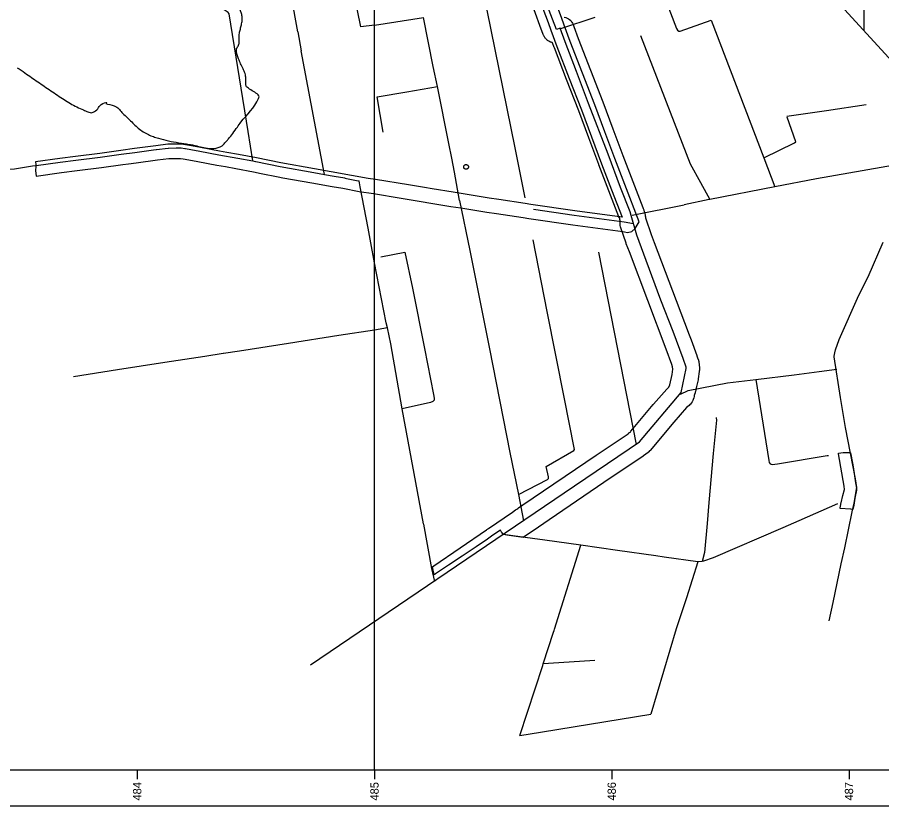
# Model space of a CAD drawing. Extents: x 468834 to 503362, y 294936 to 320859.
# Drawn here: x 483494 to 487137, y 294936 to 298258 of the extents above; entities that cross this region are included whole.
import ezdxf

# ---------------------------------------------------------------- set-up
doc = ezdxf.new("R2010")
doc.units = 0
for name, color, linetype in [('7311020103_no 10 līdz 25 kilometriem garas dabiskas ūdensteces vides un dabas resursu aizsardzības aizsargjoslas teritorija lauku apvidos', 7, 'Continuous'), ('7311080102_vides un dabas resursu aizsardzības aizsargjoslas teritorija ap purvu ar platību lielāku par 100 hektāriem', 7, 'Continuous'), ('7311090700_stingra režīma vides un dabas resursu aizsardzības aizsargjoslas teritorija ap pazemes ūdens ņemšanas vietu', 7, 'Continuous'), ('7312030303_ekspluatācijas aizsargjoslas teritorija gar valsts vietējiem un pašvaldību autoceļiem lauku apvidos', 7, 'Continuous'), ('7312070202_navigācijas tehniskā līdzekļa aviācijas gaisa kuģu lidojumu drošības nodrošināšanai tālās ietekmes zona', 7, 'Continuous'), ('aizkrāsojums-lidlauka tālās ietekmes zona', 7, 'Continuous'), ('Koplietošanas novadgrāvis', 7, 'Continuous'), ('ramis', 7, 'Continuous'), ('Valsts nozīmes udensnotekas', 7, 'Continuous')]:
    doc.layers.add(name, color=color, linetype=linetype)

msp = doc.modelspace()

# ---------------------------------------------------------------- linework, layer by layer
at = {"layer": '7311020103_no 10 līdz 25 kilometriem garas dabiskas ūdensteces vides un dabas resursu aizsardzības aizsargjoslas teritorija lauku apvidos'}
msp.add_lwpolyline([(485799.4, 298258.6), (485805.5, 298257), (485811.4, 298254.7), (485816.9, 298251.7), (485821.9, 298248), (485826.5, 298243.7), (485830.5, 298238.9), (485831.8, 298236.8), (485833.9, 298233.6), (485836.6, 298227.9), (485837, 298226.8), (485840, 298218.5), (485858.7, 298168.1), (485910, 298035.3), (485961.4, 297902.3), (485961.6, 297901.7), (486004.1, 297788.2), (486046.6, 297675.3), (486088.6, 297565.9), (486130.8, 297456.4), (486132.4, 297452.3), (486132.6, 297451.7), (486134.6, 297446.6), (486135.4, 297444.2), (486136.3, 297441.1), (486136.9, 297438.3), (486137.4, 297437), (486138.3, 297433.8), (486139.1, 297430.6), (486139.1, 297430.5), (486139.9, 297426.6), (486140, 297426), (486140.2, 297424.7), (486140.9, 297420.8), (486141, 297420.5), (486141, 297420.3), (486141.1, 297419.7), (486141.1, 297419.5), (486141.2, 297419.2), (486142, 297414.1), (486142.1, 297413.3), (486142.2, 297412.8), (486142.2, 297412.4), (486165.6, 297343), (486178.6, 297309), (486178.6, 297308.9), (486240.3, 297146.1), (486321.4, 296931.7), (486322, 296929.6), (486322.7, 296928.3), (486323.2, 296926.8), (486333.7, 296899.2), (486333.8, 296899), (486358.2, 296833.4), (486358.3, 296833), (486358.4, 296832.9), (486358.6, 296832.1), (486358.7, 296832), (486358.7, 296831.9), (486358.8, 296831.6), (486361.5, 296823.6), (486361.6, 296823.3), (486364.8, 296813.5), (486365.7, 296810.7), (486365.8, 296810.3), (486366, 296809.6), (486366.6, 296806.7), (486367.2, 296803.5), (486367.2, 296803), (486367.3, 296802.2), (486367.6, 296799.4), (486367.6, 296798.8), (486368.9, 296775.7), (486368.9, 296773.3), (486368.9, 296772.7), (486368.8, 296769.2), (486368.7, 296767.9), (486368.7, 296767.3), (486368.5, 296765.4), (486368.4, 296764.9), (486364.2, 296735), (486364, 296734), (486364, 296733.8), (486363.7, 296732), (486363.6, 296731.8), (486363.6, 296731.6), (486363.4, 296730.6), (486357, 296702.2), (486352.2, 296680.9), (486352.2, 296680.7), (486351.8, 296679), (486351.7, 296678.6), (486351.6, 296678.3), (486350.7, 296675.3), (486350.6, 296674.9), (486350.5, 296674.8), (486350, 296673.3), (486346.6, 296664.1), (486346.3, 296660.4), (486345.1, 296654.2), (486343.2, 296648.2), (486341.2, 296643.9), (486339.3, 296640.1), (486338.4, 296638.4), (486337.9, 296637.5), (486334.6, 296632.2), (486331.4, 296628.3), (486330.3, 296627), (486329.4, 296626), (486325.8, 296622.5), (486315.1, 296613.2), (486261.4, 296552.7), (486161.4, 296433.4), (486159.7, 296431.5), (486159.1, 296430.9), (486155.3, 296427.2), (486154.7, 296426.7), (486153.9, 296426), (486152.7, 296425), (486133.4, 296410.1), (486132.6, 296409.5), (486131, 296408.3), (486130.2, 296407.8), (485997.7, 296319.2), (485735.3, 296140.4), (485667.9, 296094.5), (485640.1, 296075.5), (485626.8, 296066.5), (485558, 296076.4), (485541.3, 296078.8), (485537.1, 296086.2), (485537, 296086.3), (485530.6, 296097.6), (485498.7, 296075.6), (485475.8, 296059.8), (485427.9, 296027), (485369.8, 295987.7), (485312.2, 295949.2), (485256.7, 295913.1), (485250.5, 295909), (485244, 295943.3), (485249.7, 295947.2), (485471.3, 296098.4), (485472.7, 296099.3), (485475.6, 296100.9), (485478, 296102.9), (485480.3, 296104.5), (485580.7, 296173), (485594.1, 296182.2), (485594.5, 296182.5), (485597.3, 296184.2), (485598.9, 296185), (485599.4, 296185.5), (485603.1, 296188.3), (485607.1, 296191), (485625, 296203.2), (485933.9, 296413.7), (486068.2, 296503.5), (486069.2, 296504.1), (486069.5, 296504.3), (486069.5, 296504.3), (486071.9, 296506.5), (486074.2, 296508.4), (486078, 296511.4), (486080.7, 296514.6), (486097.2, 296534.3), (486174.6, 296626.6), (486174.8, 296626.8), (486174.9, 296626.9), (486175.3, 296627.5), (486175.4, 296627.5), (486175.4, 296627.6), (486175.6, 296627.8), (486232.3, 296691.6), (486233.3, 296692.8), (486233.6, 296693.1), (486234.6, 296694.1), (486235.9, 296695.3), (486236.2, 296695.6), (486237.3, 296696.6), (486237.4, 296696.7), (486240, 296699), (486243.8, 296709), (486253.6, 296752.9), (486256.7, 296775.2), (486256.2, 296785.3), (486252.9, 296795.3), (486228.9, 296859.7), (486073.9, 297269.2), (486060.6, 297304.1), (486060.4, 297304.6), (486060, 297305.7), (486059.8, 297306.2), (486038, 297371.1), (486036.9, 297374.7), (486035.7, 297380.8), (486035.3, 297387.1), (486035.4, 297387.7), (486035.5, 297388.7), (486035.3, 297389.9), (486035.2, 297393.2), (486035.2, 297393.4), (486035.2, 297396.9), (486035.1, 297398.8), (486034.6, 297401.9), (486033.8, 297406.2), (486033.4, 297408.2), (486033.3, 297408.9), (486033, 297409.8), (486031.9, 297412.7), (486030.1, 297417.5), (486030, 297417.5), (485987.8, 297527.1), (485987.8, 297527.1), (485945.7, 297636.7), (485945.6, 297637), (485903, 297750.2), (485902.9, 297750.3), (485860.6, 297863.4), (485809.2, 297996.4), (485809.2, 297996.4), (485757.8, 298129.6), (485757.6, 298130.2), (485749.9, 298150.8), (485748.7, 298151.1), (485748.1, 298151.3), (485746.6, 298151.7), (485744, 298152.5), (485741, 298153.7), (485738, 298155), (485735.1, 298156.6), (485732.3, 298158.3), (485729.7, 298160.2), (485729.2, 298160.5), (485728, 298161.5), (485725.9, 298163.2), (485723.5, 298165.5), (485721.3, 298167.9), (485719.2, 298170.4), (485717.3, 298173), (485715.6, 298175.8), (485715.3, 298176.3), (485714.5, 298177.7), (485713.3, 298180.1), (485711.9, 298183.1), (485711.2, 298184.8), (485697.1, 298222.9), (485659.6, 298323.9)], dxfattribs=at)
msp.add_lwpolyline([(487019.4, 296202.7), (487015.1, 296183.8), (487007.6, 296185.5), (487006.3, 296185.6), (486962.3, 296189), (486964, 296200.5), (486964.6, 296203.6), (486964.9, 296206.4), (486965.4, 296209.7), (486966.1, 296212.6), (486974.2, 296243.5), (486980.1, 296268.4), (486979.5, 296281.8), (486955.7, 296418.7), (486955.2, 296421.4), (486964.7, 296423), (486974.6, 296423.9), (486987.2, 296424.2), (486999.4, 296423.9), (487001.5, 296423.8), (487005.7, 296423.1), (487015.4, 296371.7), (487022, 296336.3), (487027.3, 296296.4), (487030.8, 296274.7), (487031.3, 296265.3), (487024.4, 296231.6)], close=True, dxfattribs=at)
at = {"layer": '7311080102_vides un dabas resursu aizsardzības aizsargjoslas teritorija ap purvu ar platību lielāku par 100 hektāriem'}
for points in [[(484457.5, 297971.9), (484457.5, 298000), (484454, 298020.7), (484445.6, 298041.3), (484435.5, 298062.1), (484426.8, 298083.1), (484417.6, 298118.3), (484418.7, 298125.8), (484422.5, 298133.1), (484426.7, 298140.5), (484429.1, 298148.1), (484429.4, 298156.4), (484429.1, 298164.8), (484428.8, 298173.2), (484429.1, 298181.5), (484432, 298199.5), (484436.5, 298217.4), (484440.6, 298235.3), (484442.3, 298253.1), (484440.1, 298269.4), (484435, 298285.5), (484429.4, 298301.7), (484425.8, 298317.9), (484425.8, 298338), (484433, 298359.2), (484439.6, 298368), (484446.8, 298376.1), (484454, 298383.9), (484460.8, 298392.2), (484487.2, 298427.1)], [(483494.1, 298045.6), (483526.3, 298023.6), (483580.6, 297986), (483635.2, 297948.4), (483691.1, 297911), (483717.8, 297894.8), (483745.3, 297880.3), (483773, 297867.4), (483791.5, 297859.6)], [(484421.6, 297795.3), (484436.9, 297816.5), (484511.2, 297915.6), (484513.1, 297923.3), (484509.1, 297930.7), (484489.9, 297945.1), (484468, 297958.8), (484460.4, 297965.4), (484457.5, 297971.9)], [(483791.5, 297859.6), (483800.6, 297856.2), (483818.9, 297860.3), (483836.9, 297877.5), (483854.6, 297894.8), (483871.9, 297898.6), (483868.7, 297897.1), (483894.6, 297887.5), (483931.5, 297861.3), (483966.9, 297826.2), (484004.2, 297790.7), (484046.8, 297763.4), (484067.7, 297755.1), (484088.8, 297748.2), (484131.6, 297737.4), (484174.8, 297729.4), (484218, 297722.6), (484236.5, 297719), (484295.1, 297706.2), (484332.3, 297706.2), (484363.8, 297722.6), (484369.2, 297728.3), (484374.5, 297733.9), (484384.4, 297745.4), (484402.4, 297768.9), (484421.6, 297795.3)]]:
    msp.add_spline(points, degree=3, dxfattribs=at)
at = {"layer": '7311090700_stingra režīma vides un dabas resursu aizsardzības aizsargjoslas teritorija ap pazemes ūdens ņemšanas vietu'}
msp.add_lwpolyline([(485395.5, 297627.5), (485395.5, 297626.6), (485395.4, 297625.8), (485395.2, 297624.9), (485394.9, 297624.1), (485394.6, 297623.3), (485394.2, 297622.5), (485393.7, 297621.8), (485393.2, 297621.1), (485392.6, 297620.4), (485391.9, 297619.8), (485391.2, 297619.3), (485390.5, 297618.8), (485389.7, 297618.4), (485388.9, 297618.1), (485388.1, 297617.9), (485387.2, 297617.7), (485386.4, 297617.5), (485385.5, 297617.5), (485384.6, 297617.5), (485383.8, 297617.7), (485382.9, 297617.9), (485382.1, 297618.1), (485381.3, 297618.4), (485380.5, 297618.8), (485379.8, 297619.3), (485379.1, 297619.8), (485378.4, 297620.4), (485377.8, 297621.1), (485377.3, 297621.8), (485376.8, 297622.5), (485376.4, 297623.3), (485376.1, 297624.1), (485375.9, 297624.9), (485375.7, 297625.8), (485375.5, 297626.6), (485375.5, 297627.5), (485375.5, 297628.4), (485375.7, 297629.2), (485375.9, 297630.1), (485376.1, 297630.9), (485376.4, 297631.7), (485376.8, 297632.5), (485377.3, 297633.2), (485377.8, 297633.9), (485378.4, 297634.6), (485379.1, 297635.2), (485379.8, 297635.7), (485380.5, 297636.2), (485381.3, 297636.6), (485382.1, 297636.9), (485382.9, 297637.2), (485383.8, 297637.4), (485384.6, 297637.5), (485385.5, 297637.5), (485386.4, 297637.5), (485387.2, 297637.4), (485388.1, 297637.2), (485388.9, 297636.9), (485389.7, 297636.6), (485390.5, 297636.2), (485391.2, 297635.7), (485391.9, 297635.2), (485392.6, 297634.6), (485393.2, 297633.9), (485393.7, 297633.2), (485394.2, 297632.5), (485394.6, 297631.7), (485394.9, 297630.9), (485395.2, 297630.1), (485395.4, 297629.2), (485395.5, 297628.4)], close=True, dxfattribs=at)
at = {"layer": '7312030303_ekspluatācijas aizsargjoslas teritorija gar valsts vietējiem un pašvaldību autoceļiem lauku apvidos'}
for p, q in [((485742.7, 298204.1), (485768.7, 298134.1)), ((485927.7, 297888.9), (485876.1, 298022.2)), ((485970.1, 297775.5), (485927.7, 297888.9)), ((485913.9, 297754.4), (485956.6, 297641)), ((483987.6, 297704.5), (483930.4, 297696.5)), ((484203.2, 297721), (484185.6, 297723.4)), ((484604.4, 297644.1), (484501.9, 297665.8)), ((483570.2, 297648.9), (483572.3, 297637.6)), ((483571.7, 297629.2), (483570.3, 297612.7)), ((483572.3, 297637.6), (483571.7, 297629.2)), ((484254.8, 297650.4), (484335.4, 297635.3)), ((484335.4, 297635.3), (484372.1, 297628.6)), ((484372.1, 297628.6), (484415.5, 297620.6)), ((483570.3, 297612.7), (483574.3, 297588.9)), ((484415.5, 297620.6), (484490.3, 297607)), ((484490.3, 297607), (484522.5, 297600.1)), ((484522.5, 297600.1), (484593.1, 297585.2)), ((484593.1, 297585.2), (484613.2, 297581.8)), ((485004.5, 297574.5), (484973.3, 297578.7)), ((485143.3, 297551.5), (485004.5, 297574.5)), ((485211, 297540.3), (485143.3, 297551.5)), ((486114.9, 297396.7), (486054.8, 297552.9)), ((484935.1, 297523.4), (484995.5, 297515.1)), ((484995.5, 297515.1), (485112.1, 297495.9)), ((485243.3, 297535), (485211, 297540.3)), ((485331.5, 297520.4), (485243.3, 297535)), ((485373.7, 297513.7), (485331.5, 297520.4)), ((485482.9, 297496.2), (485373.7, 297513.7)), ((485523, 297490.1), (485482.9, 297496.2)), ((485634.5, 297473.1), (485523, 297490.1)), ((485659.1, 297469.5), (485634.5, 297473.1)), ((485844.3, 297443), (485659.1, 297469.5)), ((486043.4, 297415.6), (485844.3, 297443)), ((485650.6, 297410.1), (485836, 297383.6)), ((485836, 297383.6), (486045.9, 297354.7)), ((486045.9, 297354.7), (486053.2, 297353.5))]:
    msp.add_line(p, q, dxfattribs=at)
for points in [[(485627.9, 298508.9), (485628.9, 298506.4), (485661.3, 298421.5), (485693.6, 298336.7), (485731.1, 298235.5), (485742.7, 298204.1)], [(485799, 298224.9), (485787.4, 298256.4), (485749.7, 298357.8)], [(485876.1, 298022.2), (485824.8, 298155.3), (485799, 298224.9)], [(485768.7, 298134.1), (485820.2, 298000.6), (485871.6, 297867.6), (485913.9, 297754.4)], [(486054.8, 297552.9), (486012.7, 297662.4), (485970.1, 297775.5)], [(484185.6, 297723.4), (484163.5, 297723.6), (484129.3, 297722.7), (484078.2, 297716.9), (483987.6, 297704.5)], [(484266, 297709.3), (484228.6, 297716.4), (484203.2, 297721)], [(484376.8, 297688.7), (484346.3, 297694.3), (484266, 297709.3)], [(483930.4, 297696.5), (483841.4, 297684.5), (483739.1, 297671.5), (483672.9, 297662.8), (483570.2, 297648.9)], [(483963.2, 297640.5), (483995.8, 297645), (484085.6, 297657.4), (484133.4, 297662.8), (484164, 297663.6)], [(484164, 297663.6), (484181.3, 297663.4), (484193.9, 297661.7)], [(484193.9, 297661.7), (484217.7, 297657.4), (484254.8, 297650.4)], [(484501.9, 297665.8), (484426.3, 297679.6), (484376.8, 297688.7)], [(483574.3, 297588.9), (483680.8, 297603.3), (483746.8, 297612), (483849.2, 297625), (483938.5, 297637), (483963.2, 297640.5)], [(484973.3, 297578.7), (484746.1, 297619.8), (484604.4, 297644.1)], [(485956.6, 297641), (485998.8, 297531.3), (486043.4, 297415.6)], [(484613.2, 297581.8), (484735.7, 297560.7), (484821.4, 297545.2), (484866.8, 297537.3), (484935.1, 297523.4)], [(485112.1, 297495.9), (485321.8, 297461.2), (485364.2, 297454.4)], [(485364.2, 297454.4), (485473.7, 297436.9), (485513.9, 297430.8)], [(485513.9, 297430.8), (485625.7, 297413.7), (485650.6, 297410.1)], [(486084.5, 297355.5), (486098.1, 297367.6), (486114.9, 297396.7)], [(486053.2, 297353.5), (486066.6, 297351.4), (486084.5, 297355.5)]]:
    msp.add_lwpolyline(points, dxfattribs=at)
at = {"layer": '7312070202_navigācijas tehniskā līdzekļa aviācijas gaisa kuģu lidojumu drošības nodrošināšanai tālās ietekmes zona'}
msp.add_lwpolyline([(491342.5, 295086.2), (490381.1, 295586.7), (489277.5, 296289.8), (488239.3, 297086.4), (487274.5, 297970.5), (485919.8, 299448.9)], dxfattribs=at)
at = {"layer": 'aizkrāsojums-lidlauka tālās ietekmes zona'}
msp.add_line((487063, 298201.3), (487063, 314125.2), dxfattribs=at)
at = {"layer": 'Koplietošanas novadgrāvis'}
for points in [[(485303, 299119.7), (485383.5, 298729.1), (485439.5, 298454.4), (485590.7, 297708.4)], [(484941.9, 298217.5), (484811.9, 298857.6)], [(484676.1, 298196.9), (484620.3, 298507.9), (484575.6, 298746.9), (484572, 298753.8), (484569.6, 298757)], [(486190.1, 298428.3), (486272.9, 298210.9), (486276.8, 298203.7), (486282.5, 298199.3), (486288, 298199.3), (486418.3, 298245.7)], [(484466.7, 297777), (484387.1, 298272.1), (484383.2, 298278.3), (484345, 298303)], [(485000, 298224.7), (485206.7, 298257.1)], [(485264.6, 297966.3), (485247.6, 298051.2), (485206.7, 298257.1)], [(485785.2, 298211.1), (485930.4, 298258.6)], [(486418.3, 298245.7), (486640.3, 297666.3)], [(485000, 298224.7), (484941.9, 298217.5)], [(484676.1, 298196.9), (484691, 298116.9)], [(486121.2, 298181.3), (486329.6, 297640.5), (486373.5, 297562.1), (486412.6, 297490.7)], [(484788.4, 297596.2), (484691, 298116.9)], [(485136.3, 297944.4), (485264.6, 297966.3)], [(485312.7, 297725.8), (485264.6, 297966.3)], [(485036, 297773.8), (485010.3, 297923), (485136.3, 297944.4)], [(487072, 297888.5), (486904.5, 297864.4)], [(486904.5, 297864.4), (486738, 297840.4)], [(486640.3, 297666.3), (486769.9, 297728.7), (486775.3, 297732.8), (486739.1, 297837.5)], [(484486.7, 297652.6), (484466.7, 297777)], [(483573.6, 297633.5), (483674.9, 297647.2), (483675, 297647.2), (483675, 297647.2), (483741.1, 297655.8), (483741.1, 297655.8), (483741.1, 297655.8), (483843.5, 297668.9), (483932.5, 297680.9), (483989.7, 297688.9), (483989.7, 297688.9), (484067.6, 297699.6)], [(484067.6, 297699.6), (484080, 297701.3), (484080.2, 297701.3), (484080.3, 297701.3), (484129.9, 297706.9), (484130.4, 297706.9), (484130.9, 297707), (484163.4, 297707.8), (484163.6, 297707.8), (484163.8, 297707.8), (484183.8, 297707.6), (484184.5, 297707.6), (484185.2, 297707.5), (484200.5, 297705.5), (484200.7, 297705.5), (484201, 297705.4), (484203.4, 297705)], [(484203.4, 297705), (484225.7, 297701), (484225.8, 297701), (484225.8, 297700.9), (484263, 297693.9), (484343.5, 297678.8), (484423.5, 297664.2), (484486.7, 297652.6)], [(485324.9, 297664.5), (485312.7, 297725.8)], [(485590.7, 297708.4), (485632.8, 297497.2)], [(485358.4, 297485.7), (485336.6, 297604.9), (485324.9, 297664.5)], [(486640.3, 297666.3), (486687.4, 297543.3)], [(487351.1, 297662.7), (486863.2, 297576.9), (486687.4, 297543.3)], [(483462.5, 297617.3), (483482.5, 297619.7), (483558.5, 297631.4), (483558.6, 297631.4), (483558.7, 297631.4), (483573.6, 297633.5)], [(484486.7, 297652.6), (484498.7, 297650.4), (484498.8, 297650.4), (484499, 297650.3), (484601.4, 297628.7), (484743.3, 297604.3), (484743.3, 297604.3), (484743.4, 297604.3), (484788.4, 297596.2)], [(484788.4, 297596.2), (484829.2, 297588.8), (484874.8, 297580.8), (484875, 297580.8), (484875.2, 297580.7), (484930.4, 297569.5), (484934.7, 297568.7)], [(484984.4, 297307.9), (484973.1, 297368.9), (484939.7, 297543.6), (484934.7, 297568.7)], [(486687.4, 297543.3), (486412.6, 297490.7)], [(485358.4, 297485.7), (485401.8, 297275.4), (485484, 296860.4), (485570.1, 296424.7), (485606, 296247)], [(486412.6, 297490.7), (486410, 297490.2), (486304.6, 297467.5)], [(485670.3, 297449), (485841.7, 297424.5), (486051.9, 297395.5), (486052, 297395.5), (486052.1, 297395.5), (486091, 297389.2)], [(486085.1, 297424), (486304.4, 297467.5), (486304.6, 297467.5)], [(485000, 297223.1), (484984.4, 297307.9)], [(485840, 296433.3), (485842.5, 296437.5), (485841.8, 296444.1), (485800.1, 296650), (485727.8, 297018.6), (485668.3, 297319.8)], [(485025.7, 297249.2), (485127, 297267.7), (485160.3, 297117), (485210.3, 296862.6)], [(485944.4, 297267.7), (486101.9, 296457.8)], [(485053.8, 296948.9), (485049, 296971.1), (485000, 297223.1)], [(485000, 296940.3), (484850, 296917)], [(485053.8, 296948.9), (485000, 296940.3)], [(485116.2, 296608.4), (485068.3, 296882.5), (485053.8, 296948.9)], [(484850, 296917), (484637.5, 296884)], [(484637.5, 296884), (484431, 296851.8)], [(485210.3, 296862.6), (485248.4, 296669.1), (485251.4, 296652.6)], [(484284.2, 296829), (484115.6, 296802.8)], [(484361.9, 296841.1), (484284.2, 296829)], [(484431, 296851.8), (484363.4, 296841.3)], [(484115.6, 296802.8), (483916.9, 296771.9)], [(483916.9, 296771.9), (483731.1, 296743)], [(486607.4, 296732.4), (486768.1, 296752.2)], [(486768.1, 296752.2), (486874.3, 296765.3)], [(486874.3, 296765.3), (486948.8, 296774.9)], [(486288.8, 296669.5), (486321.6, 296685.1), (486487.7, 296717.7)], [(486487.7, 296717.7), (486607.4, 296732.4)], [(486607.4, 296732.4), (486661.4, 296390.1)], [(485251.4, 296652.6), (485250.8, 296644.8), (485245.1, 296638.5), (485235.8, 296634.9), (485116.2, 296608.4)], [(485206.5, 296124.3), (485116.2, 296608.4)], [(486439.7, 296571.7), (486440.2, 296570.8), (486441.7, 296559.9), (486426.7, 296419.6), (486409, 296214.1)], [(485723.8, 296365.2), (485840, 296433.3)], [(486661.4, 296390.1), (486662.9, 296382), (486667.5, 296376.9), (486675.7, 296374.3), (486698.6, 296375.9), (486908, 296411.5), (486912.9, 296412.3)], [(485606, 296247), (485728.6, 296310.8), (485733, 296314.7), (485733, 296317.1), (485733, 296321.4), (485723.8, 296365.2)], [(485606, 296247), (485628.3, 296136.5)], [(486409, 296214.1), (486401.4, 296125.6)], [(486950.7, 296208.6), (486787.7, 296136.3), (486720, 296107.2)], [(485253.4, 295880.9), (485241.8, 295935.1), (485206.9, 296122.4)], [(486401.4, 296125.6), (486390.8, 296003.1), (486380.9, 295965.4)], [(486720, 296107.2), (486427.6, 295981.2), (486386.7, 295965.8), (486380.9, 295965.4)], [(485582.6, 296073.5), (485543.9, 296078.9)], [(485717.3, 296054.6), (485582.6, 296073.5)], [(485869, 296033.2), (485717.3, 296054.6)], [(485758.3, 295679.9), (485869, 296033.2)], [(486023.2, 296011.5), (485869, 296033.2)], [(486185.7, 295988.7), (486023.2, 296011.5)], [(486220.8, 295983.7), (486185.7, 295988.7)], [(486361.9, 295963.9), (486315.2, 295812.7), (486271.7, 295681.4), (486164.3, 295322)], [(486361.9, 295963.9), (486220.8, 295983.7)], [(486380.9, 295965.4), (486361.9, 295963.9)], [(485711, 295533.3), (485754.2, 295667.4)], [(485754.2, 295667.4), (485756.3, 295673.7)], [(485756.3, 295673.7), (485758.3, 295679.9)], [(485929, 295547.5), (485863.7, 295543.2)], [(485612.4, 295232.3), (485709.1, 295527.4)], [(485709.1, 295527.4), (485711, 295533.3)], [(485863.7, 295543.2), (485711, 295533.3)], [(485776.2, 295258.9), (486164.3, 295322)], [(485699.9, 295246.5), (485776.2, 295258.9)], [(485612.4, 295232.3), (485699.9, 295246.5)]]:
    msp.add_lwpolyline(points, dxfattribs=at)
at = {"layer": 'ramis'}
for p, q in [((485000, 295086.2), (485000, 316660.3)), ((500923.3, 295086.2), (468983.8, 295086.2)), ((484000, 295086.2), (484000, 295048.1)), ((485000, 295086.2), (485000, 295048.1)), ((486000, 295086.2), (486000, 295048.1)), ((487000, 295086.2), (487000, 295048.1))]:
    msp.add_line(p, q, dxfattribs=at)
msp.add_lwpolyline([(501073.3, 316810.3), (468833.8, 316810.3), (468833.8, 294936.2), (501073.3, 294936.2)], close=True, dxfattribs=at)
at = {"layer": 'Valsts nozīmes udensnotekas'}
for points in [[(484730.2, 295529.7), (485798.6, 296253.9), (486117, 296469.7), (486292.3, 296677.4), (486312.9, 296778), (486312.8, 296784.5), (486300.8, 296820.9), (486258.6, 296934.6), (486206.4, 297065.4), (486144.5, 297233.2), (486105.9, 297339.5), (486094, 297378.9), (486089.8, 297393.7), (486081.5, 297423.3), (486077.6, 297438), (486037.1, 297541.2), (485984.2, 297680.6), (485902.1, 297894.8), (485850.9, 298029.4), (485803.5, 298154.6), (485782, 298211.6), (485766.4, 298206.2), (485644.5, 298524.2)], [(486915.7, 295714.5), (486932.4, 295792), (486966.3, 295955.2), (486981.4, 296022.3), (487012.7, 296174.7), (487021.9, 296211.4), (487032.9, 296277.4), (487027.3, 296313.1), (486985.5, 296529.5), (486963.7, 296656.6), (486936.8, 296827.6), (486937.3, 296830.4), (486940.2, 296843.9), (486943.1, 296857.2), (486957.7, 296900.1), (487041.6, 297086.5), (487079.9, 297164), (487143.9, 297310.5)]]:
    msp.add_lwpolyline(points, dxfattribs=at)

# ---------------------------------------------------------------- texts
at = {"layer": 'ramis'}
for s, p in [('484', (484017, 294957.8)), ('485', (485017, 294957.8)), ('486', (486017, 294957.8)), ('487', (487017, 294957.8))]:
    msp.add_text(s, height=35, rotation=90, dxfattribs=at).set_placement(p)

doc.saveas('drawing.dxf')
